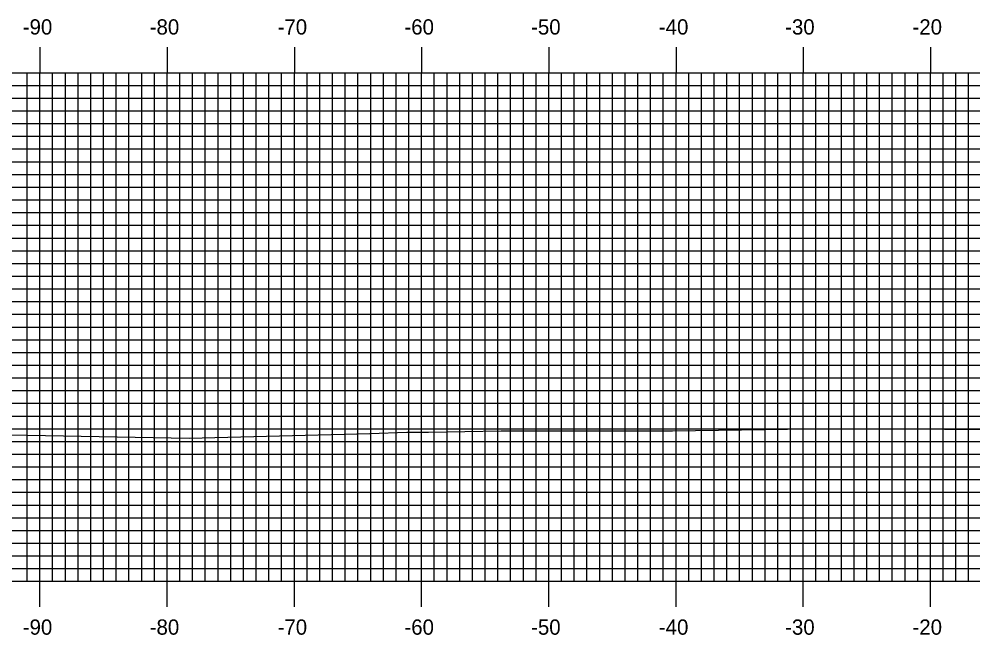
# Model space of a CAD drawing. Extents: x 852542 to 852886, y 364366 to 364586.
# Drawn here: x 852616.5 to 852691.5, y 364434.6 to 364483 of the extents above; entities that cross this region are included whole.
import ezdxf

# ---------------------------------------------------------------- set-up
doc = ezdxf.new("R2010")
doc.units = 0
for name, color, linetype in [('H_V ANNOTATION', 7, 'Continuous'), ('MAJOR', 7, 'Continuous'), ('MINOR', 7, 'Continuous'), ('S_Roadway_Centerline', 7, 'Continuous')]:
    doc.layers.add(name, color=color, linetype=linetype)

msp = doc.modelspace()

# ---------------------------------------------------------------- linework, layer by layer
at = {"layer": 'MAJOR'}
for p, q in [((852618.178, 364480.791), (852618.178, 364478.787)), ((852628.178, 364480.791), (852628.178, 364478.787)), ((852638.178, 364480.791), (852638.178, 364478.787)), ((852648.178, 364480.791), (852648.178, 364478.787)), ((852658.178, 364480.791), (852658.178, 364478.787)), ((852668.178, 364480.791), (852668.178, 364478.787)), ((852678.178, 364480.791), (852678.178, 364478.787)), ((852688.178, 364480.791), (852688.178, 364478.787)), ((852568.178, 364478.787), (852848.178, 364478.787)), ((852568.178, 364478.787), (852848.178, 364478.787)), ((852618.178, 364438.787), (852618.178, 364478.787)), ((852628.178, 364438.787), (852628.178, 364478.787)), ((852638.178, 364438.787), (852638.178, 364478.787)), ((852648.178, 364438.787), (852648.178, 364478.787)), ((852658.178, 364438.787), (852658.178, 364478.787)), ((852668.178, 364438.787), (852668.178, 364478.787)), ((852678.178, 364438.787), (852678.178, 364478.787)), ((852688.178, 364438.787), (852688.178, 364478.787)), ((852568.178, 364473.787), (852848.178, 364473.787)), ((852568.178, 364468.787), (852848.178, 364468.787)), ((852568.178, 364463.787), (852848.178, 364463.787)), ((852568.178, 364458.787), (852848.178, 364458.787)), ((852568.178, 364453.787), (852848.178, 364453.787)), ((852568.178, 364448.787), (852848.178, 364448.787)), ((852568.178, 364443.787), (852848.178, 364443.787)), ((852568.178, 364438.787), (852848.178, 364438.787)), ((852568.178, 364438.787), (852848.178, 364438.787)), ((852618.178, 364436.783), (852618.178, 364438.787)), ((852628.178, 364436.783), (852628.178, 364438.787)), ((852638.178, 364436.783), (852638.178, 364438.787)), ((852648.178, 364436.783), (852648.178, 364438.787)), ((852658.178, 364436.783), (852658.178, 364438.787)), ((852668.178, 364436.783), (852668.178, 364438.787)), ((852678.178, 364436.783), (852678.178, 364438.787)), ((852688.178, 364436.783), (852688.178, 364438.787))]:
    msp.add_line(p, q, dxfattribs=at)
at = {"layer": 'MINOR'}
for p, q in [((852617.178, 364438.787), (852617.178, 364478.787)), ((852619.178, 364438.787), (852619.178, 364478.787)), ((852620.178, 364438.787), (852620.178, 364478.787)), ((852621.178, 364438.787), (852621.178, 364478.787)), ((852622.178, 364438.787), (852622.178, 364478.787)), ((852623.178, 364438.787), (852623.178, 364478.787)), ((852624.178, 364438.787), (852624.178, 364478.787)), ((852625.178, 364438.787), (852625.178, 364478.787)), ((852626.178, 364438.787), (852626.178, 364478.787)), ((852627.178, 364438.787), (852627.178, 364478.787)), ((852629.178, 364438.787), (852629.178, 364478.787)), ((852630.178, 364438.787), (852630.178, 364478.787)), ((852631.178, 364438.787), (852631.178, 364478.787)), ((852632.178, 364438.787), (852632.178, 364478.787)), ((852633.178, 364438.787), (852633.178, 364478.787)), ((852634.178, 364438.787), (852634.178, 364478.787)), ((852635.178, 364438.787), (852635.178, 364478.787)), ((852636.178, 364438.787), (852636.178, 364478.787)), ((852637.178, 364438.787), (852637.178, 364478.787)), ((852639.178, 364438.787), (852639.178, 364478.787)), ((852640.178, 364438.787), (852640.178, 364478.787)), ((852641.178, 364438.787), (852641.178, 364478.787)), ((852642.178, 364438.787), (852642.178, 364478.787)), ((852643.178, 364438.787), (852643.178, 364478.787)), ((852644.178, 364438.787), (852644.178, 364478.787)), ((852645.178, 364438.787), (852645.178, 364478.787)), ((852646.178, 364438.787), (852646.178, 364478.787)), ((852647.178, 364438.787), (852647.178, 364478.787)), ((852649.178, 364438.787), (852649.178, 364478.787)), ((852650.178, 364438.787), (852650.178, 364478.787)), ((852651.178, 364438.787), (852651.178, 364478.787)), ((852652.178, 364438.787), (852652.178, 364478.787)), ((852653.178, 364438.787), (852653.178, 364478.787)), ((852654.178, 364438.787), (852654.178, 364478.787)), ((852655.178, 364438.787), (852655.178, 364478.787)), ((852656.178, 364438.787), (852656.178, 364478.787)), ((852657.178, 364438.787), (852657.178, 364478.787)), ((852659.178, 364438.787), (852659.178, 364478.787)), ((852660.178, 364438.787), (852660.178, 364478.787)), ((852661.178, 364438.787), (852661.178, 364478.787)), ((852662.178, 364438.787), (852662.178, 364478.787)), ((852663.178, 364438.787), (852663.178, 364478.787)), ((852664.178, 364438.787), (852664.178, 364478.787)), ((852665.178, 364438.787), (852665.178, 364478.787)), ((852666.178, 364438.787), (852666.178, 364478.787)), ((852667.178, 364438.787), (852667.178, 364478.787)), ((852669.178, 364438.787), (852669.178, 364478.787)), ((852670.178, 364438.787), (852670.178, 364478.787)), ((852671.178, 364438.787), (852671.178, 364478.787)), ((852672.178, 364438.787), (852672.178, 364478.787)), ((852673.178, 364438.787), (852673.178, 364478.787)), ((852674.178, 364438.787), (852674.178, 364478.787)), ((852675.178, 364438.787), (852675.178, 364478.787)), ((852676.178, 364438.787), (852676.178, 364478.787)), ((852677.178, 364438.787), (852677.178, 364478.787)), ((852679.178, 364438.787), (852679.178, 364478.787)), ((852680.178, 364438.787), (852680.178, 364478.787)), ((852681.178, 364438.787), (852681.178, 364478.787)), ((852682.178, 364438.787), (852682.178, 364478.787)), ((852683.178, 364438.787), (852683.178, 364478.787)), ((852684.178, 364438.787), (852684.178, 364478.787)), ((852685.178, 364438.787), (852685.178, 364478.787)), ((852686.178, 364438.787), (852686.178, 364478.787)), ((852687.178, 364438.787), (852687.178, 364478.787)), ((852689.178, 364438.787), (852689.178, 364478.787)), ((852690.178, 364438.787), (852690.178, 364478.787)), ((852691.178, 364438.787), (852691.178, 364478.787)), ((852568.178, 364477.787), (852848.178, 364477.787)), ((852568.178, 364476.787), (852848.178, 364476.787)), ((852568.178, 364475.787), (852848.178, 364475.787)), ((852568.178, 364474.787), (852848.178, 364474.787)), ((852568.178, 364472.787), (852848.178, 364472.787)), ((852568.178, 364471.787), (852848.178, 364471.787)), ((852568.178, 364470.787), (852848.178, 364470.787)), ((852568.178, 364469.787), (852848.178, 364469.787)), ((852568.178, 364467.787), (852848.178, 364467.787)), ((852568.178, 364466.787), (852848.178, 364466.787)), ((852568.178, 364465.787), (852848.178, 364465.787)), ((852568.178, 364464.787), (852848.178, 364464.787)), ((852568.178, 364462.787), (852848.178, 364462.787)), ((852568.178, 364461.787), (852848.178, 364461.787)), ((852568.178, 364460.787), (852848.178, 364460.787)), ((852568.178, 364459.787), (852848.178, 364459.787)), ((852568.178, 364457.787), (852848.178, 364457.787)), ((852568.178, 364456.787), (852848.178, 364456.787)), ((852568.178, 364455.787), (852848.178, 364455.787)), ((852568.178, 364454.787), (852848.178, 364454.787)), ((852568.178, 364452.787), (852848.178, 364452.787)), ((852568.178, 364451.787), (852848.178, 364451.787)), ((852568.178, 364450.787), (852848.178, 364450.787)), ((852568.178, 364449.787), (852848.178, 364449.787)), ((852568.178, 364447.787), (852848.178, 364447.787)), ((852568.178, 364446.787), (852848.178, 364446.787)), ((852568.178, 364445.787), (852848.178, 364445.787)), ((852568.178, 364444.787), (852848.178, 364444.787)), ((852568.178, 364442.787), (852848.178, 364442.787)), ((852568.178, 364441.787), (852848.178, 364441.787)), ((852568.178, 364440.787), (852848.178, 364440.787)), ((852568.178, 364439.787), (852848.178, 364439.787))]:
    msp.add_line(p, q, dxfattribs=at)
at = {"layer": 'S_Roadway_Centerline'}
msp.add_lwpolyline([(852568.178, 364449.598), (852574.481, 364449.544), (852575.584, 364449.59), (852577.44, 364449.438), (852592.081, 364448.649), (852598.281, 364448.616), (852610.837, 364450.355), (852611.083, 364450.389), (852611.51, 364450.38), (852629.915, 364450.055), (852644.12, 364450.418), (852647.016, 364450.522), (852648.727, 364450.509), (852654.428, 364450.609), (852667.903, 364450.632), (852676.949, 364450.751), (852686.436, 364450.776), (852692.139, 364450.728)], dxfattribs=at)

# ---------------------------------------------------------------- texts
at = {"layer": 'H_V ANNOTATION'}
for s, p in [('-90', (852616.83, 364481.787)), ('-80', (852626.808, 364481.787)), ('-70', (852636.862, 364481.787)), ('-60', (852646.83, 364481.787)), ('-50', (852656.787, 364481.787)), ('-40', (852666.83, 364481.787)), ('-30', (852676.755, 364481.787)), ('-20', (852686.765, 364481.787)), ('-90', (852616.83, 364434.587)), ('-80', (852626.808, 364434.587)), ('-70', (852636.862, 364434.587)), ('-60', (852646.83, 364434.587)), ('-50', (852656.787, 364434.587)), ('-40', (852666.83, 364434.587)), ('-30', (852676.755, 364434.587)), ('-20', (852686.765, 364434.587))]:
    msp.add_text(s, height=1.2, dxfattribs=at).set_placement(p)

doc.saveas('drawing.dxf')
